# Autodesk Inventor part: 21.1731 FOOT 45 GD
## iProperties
Created: 2007-04
Part Number: 21.1731 FOOT 45 GD
Document SubType Name: Modeling
Designer: Andy Moles
Material: Aluminum-6061
Mass: 502.121 g
Surface Area: 838.547 cm^2
Volume: 185.284 cm^3
Density: 2.71 g/cm^3
Author: Andy Moles
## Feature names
1. Base1
2. Hole1
